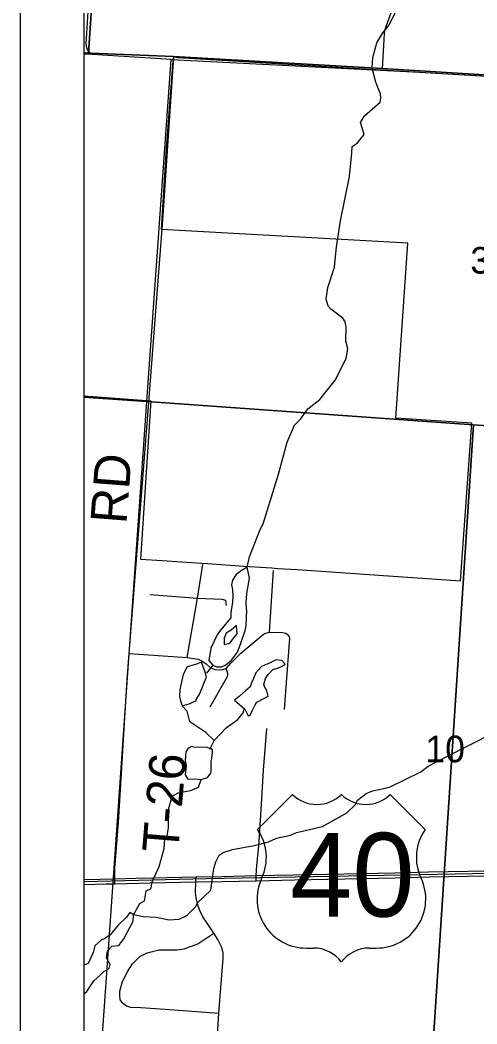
# Model space of a CAD drawing. Extents: x 0 to 34, y 0 to 22.
# Drawn here: x 2 to 2.718, y 16.964 to 18.544 of the extents above; entities that cross this region are included whole.
import ezdxf

# ---------------------------------------------------------------- set-up
doc = ezdxf.new("R2010")
doc.units = 0
for name, color, linetype in [('GM_X_City_Street', 7, 'Continuous'), ('GM_X_Corporation', 7, 'Continuous'), ('GM_X_Minor_Lake', 7, 'Continuous'), ('GM_X_Minor_River', 7, 'Continuous'), ('GM_X_Rail_Line', 7, 'Continuous'), ('GM_X_Section', 7, 'Continuous'), ('GM_X_Section_Text', 7, 'Continuous'), ('GM_X_Township_Road', 7, 'Continuous'), ('GM_X_Township_Road_Text', 7, 'Continuous'), ('GM_X_Unincorporated_Text', 7, 'Continuous'), ('GM_X_US_Location', 7, 'Continuous'), ('GM_X_US_Route', 7, 'Continuous'), ('GM_X_US_Shield', 7, 'Continuous'), ('SH_Cut_Line', 7, 'Continuous'), ('SH_Data', 7, 'Continuous')]:
    doc.layers.add(name, color=color, linetype=linetype)

msp = doc.modelspace()

# ---------------------------------------------------------------- linework, layer by layer
at = {"layer": 'GM_X_City_Street'}
msp.add_line((2.1, 18.4924), (2.1113, 18.4919), dxfattribs=at)
for points in [[(8.3697, 20.9), (2.1, 20.9), (2.1, 18.8151), (2.1233, 18.8137), (2.129, 18.8133), (2.1078, 18.4924), (2.1111, 18.4924), (2.2415, 18.4869), (2.2482, 18.4853), (3.4177, 18.4149), (4.6284, 18.3336)], [(2.5698, 18.4675), (2.572, 18.5044), (2.5733, 18.5234), (2.5745, 18.5319), (2.5818, 18.5516), (2.5822, 18.5528), (2.5924, 18.5726), (2.5935, 18.5749), (2.595, 18.5791), (2.5958, 18.5825), (2.5965, 18.5867), (2.5972, 18.5943), (2.5945, 18.6144)]]:
    msp.add_lwpolyline(points, dxfattribs=at)
msp.add_lwpolyline([(2.1, 18.8151), (2.1, 17.9527), (2.1987, 17.9456), (2.2055, 17.9452), (2.1895, 17.696), (2.2235, 17.6937), (2.2851, 17.6893), (2.2946, 17.6889), (2.3519, 17.685), (2.3959, 17.682), (2.4054, 17.681), (2.436, 17.6793), (2.6928, 17.6619), (2.7103, 17.9098), (2.5909, 17.9177), (2.6098, 18.193), (2.2223, 18.215), (2.2305, 18.3429), (2.2415, 18.4869), (2.1111, 18.4924), (2.1078, 18.4924), (2.129, 18.8133), (2.1233, 18.8137)], close=True, dxfattribs=at)
at = {"layer": 'GM_X_Corporation'}
for points in [[(6.4385, 20.9), (2.1, 20.9), (2.1, 18.4929), (2.1111, 18.4924), (2.2415, 18.4869), (2.5696, 18.468), (3.4218, 18.4152), (4.6285, 18.3373)], [(4.6285, 18.3373), (3.4218, 18.4152), (2.5696, 18.468), (2.2415, 18.4869), (2.1111, 18.4924), (2.1, 18.4929), (2.1, 15.9442), (2.2903, 15.9292), (2.5827, 15.9132), (2.6921, 15.9056), (2.7799, 15.8989), (2.8362, 15.8952), (3.3132, 15.8609), (3.9945, 15.8088)]]:
    msp.add_lwpolyline(points, dxfattribs=at)
at = {"layer": 'GM_X_Minor_Lake'}
for points in [[(2.357, 17.6831), (2.3479, 17.6774), (2.3396, 17.6718), (2.3342, 17.663), (2.3323, 17.6555), (2.3338, 17.6479), (2.3346, 17.6369), (2.3342, 17.6281), (2.3319, 17.6152), (2.3315, 17.6111), (2.3315, 17.6042), (2.3315, 17.6035), (2.325, 17.5959), (2.3212, 17.591), (2.3144, 17.5834), (2.3102, 17.5766), (2.2999, 17.5557), (2.2969, 17.5364), (2.3033, 17.5291)], [(2.3033, 17.5291), (2.309, 17.5261), (2.3166, 17.5261), (2.3238, 17.5295), (2.3325, 17.537), (2.342, 17.5492), (2.3473, 17.5636), (2.3538, 17.5833), (2.3553, 17.5916), (2.3565, 17.6156), (2.3561, 17.6167), (2.3558, 17.6281), (2.3565, 17.641), (2.3588, 17.6539), (2.3608, 17.666), (2.357, 17.6831)], [(2.3402, 17.5913), (2.3322, 17.5841), (2.3239, 17.5792), (2.3208, 17.5712), (2.3208, 17.5617)], [(2.3299, 17.5636), (2.3325, 17.5666), (2.3325, 17.567), (2.3413, 17.5784), (2.3402, 17.5913)], [(2.3208, 17.5617), (2.3299, 17.5636)], [(2.2854, 17.5337), (2.2775, 17.5306), (2.2627, 17.5265), (2.2566, 17.514), (2.2513, 17.4908), (2.2509, 17.4794), (2.2524, 17.473), (2.2551, 17.465), (2.2657, 17.468)], [(2.2657, 17.468), (2.2774, 17.4733), (2.2766, 17.4741), (2.2819, 17.4832), (2.2861, 17.4934), (2.2895, 17.5014), (2.293, 17.5098), (2.2911, 17.5181), (2.2854, 17.5337)], [(2.3899, 17.4804), (2.3873, 17.4906), (2.385, 17.494), (2.3835, 17.4986), (2.3862, 17.5077), (2.39, 17.5141), (2.3976, 17.5221), (2.4063, 17.5247), (2.4131, 17.5281), (2.4169, 17.5304), (2.4116, 17.5365), (2.4029, 17.5373), (2.3934, 17.5327), (2.3798, 17.5271), (2.3707, 17.5168), (2.3673, 17.5077), (2.3638, 17.5009), (2.3619, 17.4948), (2.3547, 17.4888), (2.3445, 17.4797), (2.3373, 17.4736), (2.3535, 17.4596)], [(2.3535, 17.4596), (2.3588, 17.4493), (2.3618, 17.45), (2.3656, 17.458), (2.3698, 17.4664), (2.3725, 17.4709), (2.3835, 17.4766), (2.3899, 17.4804)], [(2.3003, 17.3739), (2.3004, 17.3777), (2.3015, 17.3819), (2.3026, 17.3917), (2.3026, 17.3955), (2.2932, 17.4001), (2.2822, 17.3993), (2.2731, 17.3997), (2.269, 17.4009), (2.2637, 17.3975), (2.2606, 17.3925), (2.2595, 17.3789), (2.261, 17.3705), (2.2595, 17.3561), (2.264, 17.3493), (2.275, 17.35), (2.2848, 17.3492)], [(2.2848, 17.3492), (2.2946, 17.3523), (2.3, 17.3591), (2.3003, 17.361), (2.3007, 17.3682), (2.3003, 17.3739)], [(2.1786, 17.1361), (2.1767, 17.1372), (2.1726, 17.1395), (2.1676, 17.1323), (2.154, 17.1198), (2.1415, 17.1046), (2.1328, 17.0982), (2.1279, 17.0967), (2.1176, 17.0872), (2.115, 17.0766), (2.107, 17.0595), (2.1, 17.0568)], [(2.1, 17.0117), (2.1051, 17.0151), (2.116, 17.0322), (2.1267, 17.0413), (2.1316, 17.047), (2.1399, 17.0515), (2.1418, 17.0576), (2.1361, 17.0682), (2.1373, 17.0792), (2.1445, 17.0868), (2.1555, 17.0879), (2.163, 17.0982), (2.1778, 17.1262), (2.1786, 17.1361)]]:
    msp.add_lwpolyline(points, dxfattribs=at)
at = {"layer": 'GM_X_Minor_River'}
for points in [[(2.357, 17.6831), (2.3608, 17.6994), (2.3776, 17.7423), (2.3825, 17.7514), (2.4065, 17.8295), (2.4199, 17.88), (2.4317, 17.9065), (2.4408, 17.9164), (2.4526, 17.9327), (2.4715, 17.947), (2.4837, 17.9622), (2.4954, 17.9777), (2.5126, 18.0115), (2.5156, 18.027), (2.5122, 18.0388), (2.5127, 18.0616), (2.5115, 18.0692), (2.5078, 18.0752), (2.4889, 18.0893), (2.4847, 18.0943), (2.4813, 18.1049), (2.484, 18.1235), (2.4943, 18.1557), (2.4974, 18.1872), (2.5039, 18.2286), (2.5181, 18.298), (2.5215, 18.3356), (2.5223, 18.3455), (2.5303, 18.3508), (2.5409, 18.3644), (2.5353, 18.3834), (2.5417, 18.3936), (2.5664, 18.4152), (2.5675, 18.4213), (2.5668, 18.4281), (2.5626, 18.4384), (2.5596, 18.4467), (2.5536, 18.4687), (2.5548, 18.4854), (2.5609, 18.5086), (2.5704, 18.5241), (2.5795, 18.5355), (2.5913, 18.5582)], [(2.3033, 17.5291), (2.2931, 17.5166)], [(2.305, 17.4103), (2.2921, 17.4232), (2.2671, 17.4396), (2.2626, 17.4567), (2.2551, 17.465)], [(2.3026, 17.3955), (2.2996, 17.3986), (2.305, 17.4103), (2.3243, 17.4304), (2.3425, 17.4433), (2.3509, 17.4539), (2.3524, 17.4599)], [(2.2999, 17.175), (2.3049, 17.2088), (2.308, 17.2194), (2.3129, 17.2296), (2.3194, 17.2338), (2.3338, 17.2387), (2.3682, 17.2451), (2.3906, 17.2507), (2.4035, 17.2567), (2.4251, 17.2613), (2.4345, 17.2658), (2.4758, 17.2748), (2.5138, 17.2964), (2.527, 17.3092), (2.5308, 17.3164), (2.5441, 17.327), (2.5543, 17.3312), (2.5744, 17.3353), (2.582, 17.3376), (2.6301, 17.361), (2.6419, 17.3701), (2.6703, 17.3848), (2.7454, 17.423)], [(2.1786, 17.1361), (2.1885, 17.1539), (2.1957, 17.1581), (2.1983, 17.1736), (2.2059, 17.1774), (2.207, 17.1862), (2.2188, 17.2119), (2.2268, 17.2404), (2.2276, 17.2556), (2.2313, 17.2605), (2.2333, 17.273), (2.2341, 17.3038), (2.2394, 17.3227), (2.2485, 17.328), (2.2681, 17.3318), (2.2806, 17.3371), (2.2848, 17.3492)], [(2.2999, 17.175), (2.2789, 17.1549), (2.2755, 17.1481), (2.2615, 17.1345), (2.2497, 17.1284), (2.2342, 17.1273), (2.2138, 17.1315), (2.1937, 17.1327), (2.1786, 17.1361)]]:
    msp.add_lwpolyline(points, dxfattribs=at)
at = {"layer": 'GM_X_Rail_Line'}
msp.add_lwpolyline([(2.1, 17.1885), (2.293, 17.1932), (3.2433, 17.211), (3.5049, 17.2168), (5.1641, 17.2441), (5.3961, 17.2441), (6.3843, 17.2591), (6.7484, 17.272), (7.243, 17.2836), (8.0477, 17.3015), (8.4974, 17.3184), (8.9, 17.3324)], dxfattribs=at)
at = {"layer": 'GM_X_Section'}
for points in [[(2.2377, 18.4824), (2.6283, 18.4625), (3.1458, 18.432), (3.2487, 18.4259), (3.2112, 17.8728), (2.7132, 17.9071), (2.1995, 17.9442)], [(2.1995, 17.9442), (2.7132, 17.9071), (2.648, 16.9108), (2.1294, 16.9473)], [(2.7132, 17.9071), (3.2112, 17.8728), (3.1425, 16.8774), (2.648, 16.9108)]]:
    msp.add_lwpolyline(points, close=True, dxfattribs=at)
at = {"layer": 'GM_X_Township_Road'}
for p, q in [((2.2417, 18.4863), (2.1113, 18.4919)), ((2.3921, 17.5811), (2.3985, 17.678))]:
    msp.add_line(p, q, dxfattribs=at)
for points in [[(2.1113, 18.4919), (2.1077, 18.4952), (2.1048, 18.5001), (2.1037, 18.5071), (2.1102, 18.6082), (2.1223, 18.8164)], [(2.2023, 17.9429), (2.2247, 18.2295), (2.2417, 18.4863)], [(3.4221, 18.4146), (2.5698, 18.4675), (2.2417, 18.4863)], [(2.149, 17.1848), (2.149, 17.1928), (2.1492, 17.209), (2.1546, 17.2813), (2.1594, 17.3588), (2.1636, 17.4294), (2.1685, 17.5056), (2.1715, 17.5475), (2.2023, 17.9429)], [(2.2629, 17.5412), (2.2791, 17.6344), (2.2872, 17.6872)], [(2.204, 17.64), (2.2791, 17.6344), (2.3171, 17.6329), (2.3232, 17.6314), (2.3242, 17.6228)], [(2.1715, 17.5475), (2.2629, 17.5412), (2.2798, 17.5385), (2.2848, 17.5363), (2.2928, 17.5308), (2.2986, 17.526), (2.3025, 17.5238), (2.3061, 17.5222), (2.3138, 17.5216), (2.3188, 17.5222), (2.3241, 17.5235), (2.3315, 17.5321), (2.3473, 17.5479), (2.3791, 17.5748), (2.3844, 17.5789), (2.3921, 17.5811), (2.4126, 17.5803), (2.4179, 17.5792), (2.4226, 17.5756)], [(2.4159, 17.4591), (2.4234, 17.5579), (2.4242, 17.5709), (2.4226, 17.5756)], [(2.2989, 17.4632), (2.3246, 17.5086), (2.3266, 17.5119), (2.3266, 17.5158), (2.3241, 17.5235)], [(2.3715, 17.1896), (2.3714, 17.1976), (2.3723, 17.2138), (2.3754, 17.2442), (2.379, 17.3011), (2.3828, 17.3635), (2.3883, 17.429)], [(2.3085, 16.9122), (2.3125, 16.9811), (2.3163, 17.0281), (2.3193, 17.067), (2.3194, 17.0755), (2.3174, 17.0843), (2.311, 17.0972), (2.3049, 17.107), (2.2944, 17.1229), (2.2875, 17.1329), (2.2826, 17.1425), (2.2798, 17.1494), (2.277, 17.1627), (2.2761, 17.1713), (2.2765, 17.1877), (2.2769, 17.1956)], [(2.1613, 16.9972), (2.1573, 17.0019), (2.1567, 17.0097), (2.157, 17.0159), (2.1611, 17.0311), (2.1692, 17.0475), (2.1768, 17.0587), (2.1882, 17.0702), (2.1997, 17.0763), (2.2181, 17.0807), (2.2313, 17.0811), (2.2465, 17.0807), (2.2581, 17.0823), (2.2795, 17.0903), (2.3049, 17.107)], [(2.1613, 16.9972), (2.1675, 16.9928), (2.1736, 16.9905), (2.1897, 16.9899), (2.2282, 16.9873), (2.3125, 16.9811)]]:
    msp.add_lwpolyline(points, dxfattribs=at)
at = {"layer": 'GM_X_Unincorporated_Text'}
for points in [[(2.1, 18.4909), (2.1, 17.9509), (2.1995, 17.9442), (2.2377, 18.4824), (2.105, 18.4906)], [(2.1, 17.9509), (2.1, 16.9493), (2.1294, 16.9473), (2.1995, 17.9442)]]:
    msp.add_lwpolyline(points, close=True, dxfattribs=at)
at = {"layer": 'GM_X_US_Route'}
for points in [[(2.1, 17.1917), (2.1259, 17.1923), (2.149, 17.1928), (2.182, 17.1935), (2.2089, 17.1942), (2.2769, 17.1956), (2.3176, 17.1965), (2.3714, 17.1976), (2.4298, 17.1989), (2.4827, 17.2), (2.5361, 17.2012), (2.5894, 17.2023), (2.6425, 17.2036), (2.7041, 17.2047), (2.7562, 17.2059)], [(2.1, 17.1836), (2.1357, 17.1845), (2.149, 17.1848), (2.2045, 17.1861), (2.2765, 17.1877), (2.3176, 17.1884), (2.3715, 17.1896), (2.4315, 17.1909), (2.4839, 17.192), (2.5373, 17.1932), (2.5897, 17.1944), (2.6433, 17.1956), (2.7041, 17.1966), (2.757, 17.1979)]]:
    msp.add_lwpolyline(points, dxfattribs=at)
at = {"layer": 'GM_X_US_Shield'}
for p, q in [((2.4284, 17.3254), (2.3734, 17.2705)), ((2.6371, 17.2705), (2.5822, 17.3254)), ((2.4503, 17.0837), (2.4613, 17.0837)), ((2.5492, 17.0837), (2.5602, 17.0837))]:
    msp.add_line(p, q, dxfattribs=at)
for centre, radius, start, end in [((2.4668, 17.3646), 0.0549, 225.573, 314.427), ((2.5437, 17.3646), 0.0549, 225.573, 314.427), ((2.3104, 17.2264), 0.0769, 334.5471, 35.0009), ((2.7001, 17.2264), 0.0769, 144.9991, 205.4529), ((2.4495, 17.1606), 0.0769, 154.8319, 270.6383), ((2.5611, 17.1606), 0.0769, 269.3617, 25.1681), ((2.4613, 17.0288), 0.0549, 36.8699, 90), ((2.5492, 17.0288), 0.0549, 90, 143.1301)]:
    msp.add_arc(centre, radius, start, end, dxfattribs=at)
at = {"layer": 'SH_Cut_Line'}
msp.add_lwpolyline([(8.9, 15.4827), (8.9, 20.9), (2.1, 20.9), (2.1, 15.9442), (2.2903, 15.9292), (2.5827, 15.9132), (2.6921, 15.9056), (2.7799, 15.8989), (2.8362, 15.8952), (3.3132, 15.8609), (3.9945, 15.8088), (4.2803, 15.787), (4.5905, 15.7634), (4.92, 15.7429), (5.0952, 15.7318), (5.9419, 15.6782), (6.1109, 15.6683), (6.4, 15.6498), (6.624, 15.6351), (6.838, 15.6206), (7.6503, 15.5653), (8.6741, 15.4976)], close=True, dxfattribs=at)
at = {"layer": 'SH_Data'}
msp.add_line((2, 21), (2, 14), dxfattribs=at)

# ---------------------------------------------------------------- texts
at = {"layer": 'GM_X_Section_Text'}
for s, height, p in [('3', 0.0419, (2.7082, 18.1453)), ('10', 0.04186, (2.6374, 17.3761))]:
    msp.add_text(s, height=height, rotation=0, dxfattribs=at).set_placement(p)
at = {"layer": 'GM_X_Township_Road_Text'}
for s, rotation, p in [('RD', 85.5641, (2.1671, 17.7503)), ('T-26', 85.3834, (2.2486, 17.2323))]:
    msp.add_text(s, height=0.05682, rotation=rotation, dxfattribs=at).set_placement(p)
at = {"layer": 'GM_X_US_Location'}
for s in ['0', '/']:
    msp.add_text(s, height=0.000189, dxfattribs=at).set_placement((2.5052, 17.198))
msp.add_text('40', height=0.000189, rotation=0, dxfattribs=at).set_placement((2.4661, 17.1588))
at = {"layer": 'GM_X_US_Shield'}
msp.add_text('40', height=0.13184, dxfattribs=at).set_placement((2.4244, 17.1331))

doc.saveas('drawing.dxf')
